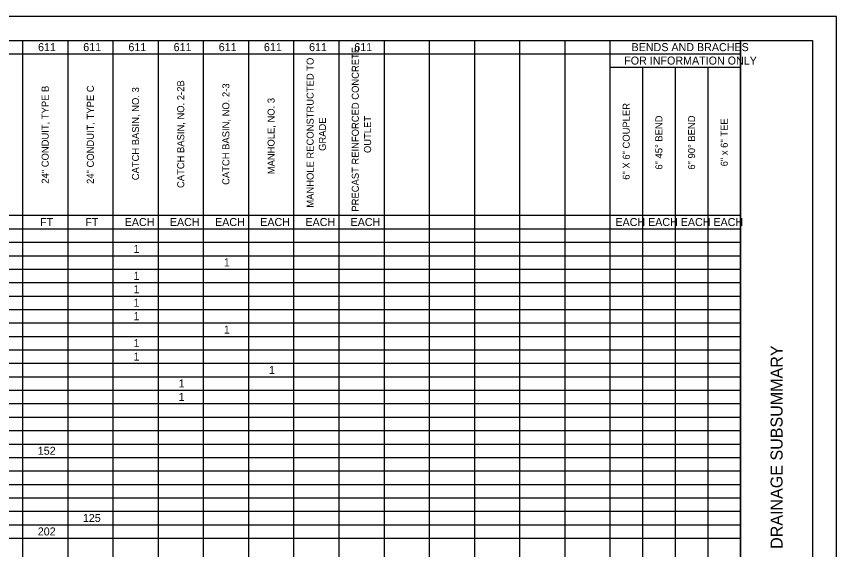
# Model space of a CAD drawing. Extents: x 0 to 34, y 0 to 22.
# Drawn here: x 16.92 to 34, y 10.9 to 22 of the extents above; entities that cross this region are included whole.
import ezdxf

# ---------------------------------------------------------------- set-up
doc = ezdxf.new("R2010")
doc.units = 0
for name, color, linetype in [('SH_Border', 7, 'Continuous'), ('SH_Cut_Line', 7, 'Continuous'), ('SH_Data', 7, 'Continuous'), ('SH_Text', 7, 'Continuous')]:
    doc.layers.add(name, color=color, linetype=linetype)

msp = doc.modelspace()

# ---------------------------------------------------------------- linework, layer by layer
at = {"layer": 'SH_Border'}
msp.add_line((32, 0.5), (32, 21.5), dxfattribs=at)
msp.add_lwpolyline([(1.5, 21.5), (33.5, 21.5), (33.5, 0.5), (1.5, 0.5)], close=True, dxfattribs=at)
at = {"layer": 'SH_Cut_Line'}
msp.add_lwpolyline([(0, 0), (34, 0), (34, 22), (0, 22)], close=True, dxfattribs=at)
at = {"layer": 'SH_Text'}
for p, q in [((1.5, 21.5), (32, 21.5)), ((17.047, 21.5), (17.047, 0.496)), ((17.988, 21.5), (17.988, 0.496)), ((18.929, 21.5), (18.929, 0.496)), ((19.869, 21.5), (19.869, 0.496)), ((20.81, 21.5), (20.81, 0.496)), ((21.751, 21.5), (21.751, 0.496)), ((22.692, 21.5), (22.692, 0.496)), ((23.633, 21.5), (23.633, 0.496)), ((24.574, 21.5), (24.574, 0.496)), ((25.515, 21.5), (25.515, 0.496)), ((26.456, 21.5), (26.456, 0.496)), ((27.397, 21.5), (27.397, 0.496)), ((28.338, 21.5), (28.338, 0.496)), ((29.279, 21.5), (29.279, 0.496)), ((32, 21.5), (32, 0.496)), ((7.638, 21.22), (32, 21.22)), ((29.279, 20.94), (32, 20.94)), ((29.959, 20.94), (29.959, 0.496)), ((30.639, 20.94), (30.639, 0.496)), ((31.32, 20.94), (31.32, 0.496)), ((7.638, 17.859), (32, 17.859)), ((1.5, 17.579), (32, 17.579)), ((1.5, 17.299), (32, 17.299)), ((1.5, 17.019), (32, 17.019)), ((1.5, 16.739), (32, 16.739)), ((1.5, 16.459), (32, 16.459)), ((1.5, 16.179), (32, 16.179)), ((1.5, 15.899), (32, 15.899)), ((1.5, 15.619), (32, 15.619)), ((1.5, 15.339), (32, 15.339)), ((1.5, 15.059), (32, 15.059)), ((1.5, 14.779), (32, 14.779)), ((1.5, 14.499), (32, 14.499)), ((1.5, 14.219), (32, 14.219)), ((1.5, 13.939), (32, 13.939)), ((1.5, 13.659), (32, 13.659)), ((1.5, 13.378), (32, 13.378)), ((1.5, 13.098), (32, 13.098)), ((1.5, 12.818), (32, 12.818)), ((1.5, 12.538), (32, 12.538)), ((1.5, 12.258), (32, 12.258)), ((1.5, 11.978), (32, 11.978)), ((1.5, 11.698), (32, 11.698)), ((1.5, 11.418), (32, 11.418)), ((1.5, 11.138), (32, 11.138))]:
    msp.add_line(p, q, dxfattribs=at)

# ---------------------------------------------------------------- texts
at = {"layer": 'SH_Data'}
msp.add_text('DRAINAGE SUBSUMMARY', height=0.25, rotation=90, dxfattribs=at).set_placement((32.875, 10.915))
at = {"layer": 'SH_Text'}
for s, height, p in [('611', 0.1667, (17.369, 21.277)), ('611', 0.1667, (18.31, 21.277)), ('611', 0.1667, (19.251, 21.277)), ('611', 0.1667, (20.192, 21.277)), ('611', 0.1667, (21.132, 21.277)), ('611', 0.1667, (22.073, 21.277)), ('611', 0.1667, (23.014, 21.277)), ('611', 0.1667, (23.955, 21.277)), ('BENDS AND BRACHES', 0.16671, (29.73, 21.277)), ('FOR INFORMATION ONLY', 0.16671, (29.577, 20.997)), ('FT', 0.1667, (17.412, 17.636)), ('FT', 0.1667, (18.353, 17.636)), ('EACH', 0.1667, (19.173, 17.636)), ('EACH', 0.1667, (20.114, 17.636)), ('EACH', 0.1667, (21.055, 17.636)), ('EACH', 0.1667, (21.996, 17.636)), ('EACH', 0.1667, (22.937, 17.636)), ('EACH', 0.1667, (23.878, 17.636)), ('EACH', 0.1667, (29.393, 17.636)), ('EACH', 0.1667, (30.073, 17.636)), ('EACH', 0.1667, (30.754, 17.636)), ('EACH', 0.1667, (31.434, 17.636)), ('1', 0.167, (19.356, 17.076)), ('1', 0.167, (21.238, 16.796)), ('1', 0.167, (19.356, 16.516)), ('1', 0.167, (19.356, 16.236)), ('1', 0.167, (19.356, 15.956)), ('1', 0.167, (19.356, 15.676)), ('1', 0.167, (21.238, 15.396)), ('1', 0.167, (19.356, 15.115)), ('1', 0.167, (19.356, 14.835)), ('1', 0.167, (22.179, 14.555)), ('1', 0.167, (20.297, 14.275)), ('1', 0.167, (20.297, 13.995)), ('152', 0.1667, (17.363, 12.875)), ('125', 0.1667, (18.302, 11.475)), ('202', 0.1667, (17.363, 11.195))]:
    msp.add_text(s, height=height, dxfattribs=at).set_placement(p)
for s, height, p in [('PRECAST REINFORCED CONCRETE ', 0.14649, (24.049, 17.936)), ('MANHOLE RECONSTRUCTED TO ', 0.14649, (23.108, 18.018)), ('24" CONDUIT, TYPE B', 0.14649, (17.59, 18.518)), ('24" CONDUIT, TYPE C', 0.14649, (18.531, 18.513)), ('CATCH BASIN, NO. 3', 0.14649, (19.472, 18.589)), ('CATCH BASIN, NO. 2-2B', 0.14649, (20.413, 18.428)), ('CATCH BASIN, NO. 2-3', 0.14649, (21.354, 18.493)), ('MANHOLE, NO. 3', 0.14649, (22.295, 18.714)), ('6" X 6" COUPLER', 0.14649, (29.692, 18.6)), ('GRADE', 0.1465, (23.364, 19.2)), ('OUTLET', 0.1465, (24.305, 19.156)), ('6" 45° BEND', 0.14649, (30.372, 18.81)), ('6" 90° BEND', 0.14649, (31.053, 18.81)), ('6" x 6" TEE', 0.14649, (31.733, 18.879))]:
    msp.add_text(s, height=height, rotation=90, dxfattribs=at).set_placement(p)

doc.saveas('drawing.dxf')
